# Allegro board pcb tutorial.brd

Outline 100 x 50 mm; copper layers: TOP, POWERPLANE_1, BOTTOM. Coordinates in mm from the lower left corner of the outline.
Outline path: rectangle 0,0 100,50

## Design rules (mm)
constraint set DEFAULT: min track width 0.127
net group DPD: nets D+ D-

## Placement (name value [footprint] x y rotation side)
C1  100uF  [1210]  6 27 0 top
C2  10uF  [0402-CAP]  13 33 270 top
C3  10uF  [0402-CAP]  35 11 180 top
C4  0.1uF  [0402-CAP]  4 22 0 top
C5  0.1uF  [0402-CAP]  4 19 0 top
C6  0.1uF  [0402-CAP]  2 38 90 top
C7  0.1uF  [0402-CAP]  34 18 90 top
C8  0.1uF  [0402-CAP]  5 38 90 top
C9  10uF  [0402-CAP]  11 25 180 top
IC1  PIC32MX440F512H  [SQFP-S-10X10-64]  22 25 90 top
JP1  -  [XTEND-DIGI-MODEM]  69 25 0 top
JP2  PIC 32 PROG  [1X06_LOCK]  11.43 15.24 0 top
MAIN_PWR  LED  [LED_LNJ]  19 5 270 top
NOREF  -  []  0 0 90 top
NOREF#2  -  [unnamed#2]  96 4 0 top
NOREF#3  -  [unnamed#2]  4 4 0 top
NOREF#4  -  []  0 0 0 top
NOREF#5  -  [unnamed#2]  4 46 0 top
NOREF#6  -  []  0 50 0 top
NOREF#7  -  []  0 0 0 top
NOREF#8  -  []  -24 -84 0 top
NOREF#9  -  [unnamed#2]  96 46 0 top
R1  150  [0402-RES]  16 5 270 top
R2  56K  [0402-RES]  35 14 0 top
U1  LT1965EMS8E-1.5PBF  [SOP65P490X110-9N]  7 33 0 top
X1  USB-B  [USB-MICROB]  19.05 46.35 180 top
Y1  8MHz  [CRYSTAL-SMD]  15 39 90 top

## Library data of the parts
C1-C9 = CAP NP
IC1 = PIC32MX440F512H
JP1 = XTEND-DIGI-MODEM
JP2 = M06_LOCK
MAIN_PWR = LED
R1 R2 = RESISTOR
U1 = LT1965EMS8E-1_0.5PBF
X1 = USB-MICROB
Y1 = CRYSTAL

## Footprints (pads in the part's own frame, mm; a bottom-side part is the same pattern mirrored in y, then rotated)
1X06_LOCK
  round 1.88 hole 1.016: 1(0,0) 2(2.54,-0.254) 3(5.08,0) 4(7.62,-0.254) 5(10.16,0) 6(12.7,-0.254)
0402-CAP
  rect 0.7x0.9 smd: 1(-0.65,0) 2(0.65,0)
0402-RES
  rect 0.7x0.9 smd: 1(-0.65,0) 2(0.65,0)
1210
  rect 1.2x2 smd: 1(-1.6,0) 2(1.6,0)
CRYSTAL-SMD
  rect 1.1x1.9 smd: 1(-1.15,1.85) 2(-1.15,-1.85) 3(1.15,-1.85) 4(1.15,1.85)
LED_LNJ
  rect 0.445x0.95 smd: 1(-0.652,0) 2(0.652,0)
SOP65P490X110-9N
  rect 1.425x0.45 smd: 1(-2.212,0.975) 2(-2.212,0.325) 3(-2.212,-0.325) 4(-2.212,-0.975) 5(2.212,-0.975) 6(2.212,-0.325) 7(2.212,0.325) 8(2.212,0.975)
  rect 1.68x1.88 smd: 9(0,0)
SQFP-S-10X10-64
  rect 1.6x0.295 smd: 1(-5.6,3.75) 2(-5.6,3.25) 3(-5.6,2.75) 4(-5.6,2.25) 5(-5.6,1.75) 6(-5.6,1.25) 7(-5.6,0.75) 8(-5.6,0.25) 9(-5.6,-0.25) 10(-5.6,-0.75) 11(-5.6,-1.25) 12(-5.6,-1.75) 13(-5.6,-2.25) 14(-5.6,-2.75) 15(-5.6,-3.25) 16(-5.6,-3.75) 33(5.6,-3.75) 34(5.6,-3.25) 35(5.6,-2.75) 36(5.6,-2.25) 37(5.6,-1.75) 38(5.6,-1.25) 39(5.6,-0.75) 40(5.6,-0.25) 41(5.6,0.25) 42(5.6,0.75) 43(5.6,1.25) 44(5.6,1.75) 45(5.6,2.25) 46(5.6,2.75) 47(5.6,3.25) 48(5.6,3.75)
  rect 0.295x1.6 smd: 17(-3.75,-5.6) 18(-3.25,-5.6) 19(-2.75,-5.6) 20(-2.25,-5.6) 21(-1.75,-5.6) 22(-1.25,-5.6) 23(-0.75,-5.6) 24(-0.25,-5.6) 25(0.25,-5.6) 26(0.75,-5.6) 27(1.25,-5.6) 28(1.75,-5.6) 29(2.25,-5.6) 30(2.75,-5.6) 31(3.25,-5.6) 32(3.75,-5.6) 49(3.75,5.6) 50(3.25,5.6) 51(2.75,5.6) 52(2.25,5.6) 53(1.75,5.6) 54(1.25,5.6) 55(0.75,5.6) 56(0.25,5.6) 57(-0.25,5.6) 58(-0.75,5.6) 59(-1.25,5.6) 60(-1.75,5.6) 61(-2.25,5.6) 62(-2.75,5.6) 63(-3.25,5.6) 64(-3.75,5.6)
unnamed#2
  round 4.064 hole 3.81: (0,0)
USB-MICROB
  rect 0.35x1.4 smd: D+(0,2.65) D-(-0.65,2.65) GND(1.3,2.65) ID(0.65,2.65) VBUS(-1.3,2.65)
  rect 1.8x1.9 smd: MT1(-3.8,0) MT2(3.8,0)
  rect 2.1x1.6 smd: MT3(-3.1,2.55) MT4(3.1,2.55)
  rect 1.9x1.9 smd: P_1(-1.2,0) P_2(1.2,0)
XTEND-DIGI-MODEM
  round 0 hole 3.3 unplated: (-26.5,14.5) (-26.5,-14.5) (26.5,14.5) (26.5,-14.5)
  round 1.422 hole 0.7: 1(-27.5,9) 2(-25.5,9) 3(-27.5,7) 4(-25.5,7) 5(-27.5,5) 6(-25.5,5) 7(-27.5,3) 8(-25.5,3) 9(-27.5,1) 10(-25.5,1) 11(-27.5,-1) 12(-25.5,-1) 13(-27.5,-3) 14(-25.5,-3) 15(-27.5,-5) 16(-25.5,-5) 17(-27.5,-7) 18(-25.5,-7) 19(-27.5,-9) 20(-25.5,-9)

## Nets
3.3V: C1.1 C4.1 C5.1 C6.1 C7.1 C8.1 IC1.10 IC1.19 IC1.26 IC1.35 IC1.38 JP2.2 R1.1 R2.1 U1.1 U1.2 U1.3
GND: C1.2 C2.2 C3.2 C4.2 C5.2 C6.2 C7.2 C8.2 C9.2 IC1.9 IC1.20 IC1.25 IC1.41 JP1.1 JP2.3 MAIN_PWR.1(CATHODE) U1.4 U1.5 U1.9 X1.GND Y1.2 Y1.4(GND_4)
VBUS: C2.1 IC1.34 JP1.2(VCC) U1.6(S\H\D\N\) U1.7 U1.8 X1.VBUS
CTS: IC1.21 JP1.9
D+: IC1.37 X1.D+
D-: IC1.36 X1.D-
PROG0: IC1.17 JP2.5
PROG1: IC1.18 JP2.4
RESET: IC1.7(_MCLR) JP2.1
RTS: IC1.29 JP1.10
SHDN: IC1.59 JP1.7
URX: IC1.31 JP1.6
UTX: IC1.32 JP1.5
N05718: C3.1 JP1.11 R2.2
N05832: MAIN_PWR.2 R1.2
N05985: IC1.39 Y1.1
N05997: IC1.40 Y1.3
N06072: C9.1 IC1.56

Pads without a net: IC1 1 2 3 4 5 6 8 11 12 13 14 15 16 22 23 24 27 28 30 33 42 43 44 45 46 47 48 49 50 51 52 53 54 55 57 58 60 61 62 63 64; JP1 3 4 8 12 13 14 15 16 17 18 19 20; JP2 6; X1 ID MT1 MT2 MT3 MT4 P_1 P_2

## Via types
v1: diameter 0.61, hole 0.33, TOP to BOTTOM, 34 vias

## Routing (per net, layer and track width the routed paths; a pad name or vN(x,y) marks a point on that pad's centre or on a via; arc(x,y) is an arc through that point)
3.3V: length 20.7
  TOP w0.28: IC1.10 v1(22.75,17.63) ; IC1.38 v1(23.25,31.83) ; IC1.19 v1(28.83,22.25) ; IC1.26 v1(29.37,25.75) ; IC1.35 v1(24.75,31.83)
  TOP w0.381: R2.1 v1(33.57,14) ; C1.1 v1(3.37,27) ; C4.1 v1(2.57,22) ; R1.1 v1(16,6.43) ; C7.1 v1(34,16.57) ; C5.1 v1(2.57,19) ; U1.3 U1.2 U1.1 v1(3.64,33.98) ; C8.1 v1(5,36.57) ; C6.1 v1(2,36.57)
  POWERPLANE_1 w0.381: JP2.2 13.97,16.1 ; JP2.2 13.97,13.87 ; JP2.2 12.85,14.99 ; JP2.2 15.09,14.99
GND: length 29.2
  TOP w0.28: IC1.9 v1(22.25,20.95) ; IC1.41 v1(21.75,31.83) ; IC1.25 v1(26.25,25.25) ; IC1.20 v1(25.62,22.75)
  TOP w0.381: X1.GND v1(17.75,42.57) ; C4.2 v1(5.43,22) ; U1.9 v1(7,34.37) ; C7.2 v1(34,19.43) ; MAIN_PWR.1 v1(19,6.31) ; Y1.2 v1(18.23,37.85) ; C1.2 v1(8.63,27) ; C5.2 v1(5.43,19) ; C2.2 v1(13,31.57) ; C8.2 v1(5,39.43) ; C3.2 v1(33.57,11) ; U1.5 v1(10.36,32.02) ; U1.4 v1(3.64,32.02) ; C6.2 v1(2,39.43) ; Y1.4 v1(13.15,41.13) ; C9.2 v1(9.57,25)
  BOTTOM w0.381: JP2.3 16.51,16.36 ; JP2.3 17.63,15.24 ; JP2.3 16.51,14.12 ; JP2.3 15.39,15.24 ; JP1.1 41.5,34.89 ; JP1.1 42.39,34 ; JP1.1 40.61,34 ; JP1.1 41.5,33.11
VBUS: length 55.8
  TOP w0.127: U1.6 U1.7 U1.8 12.03,33.98 12.36,33.65 C2.1 13.1,33.65 18.18,28.57 24.21,28.57 25.25,29.61 IC1.34 25.25,35.56 ; JP1.2 41.94,35.56 25.25,35.56 ; 25.25,35.56 25.25,38.25 24.13,39.37 22.86,39.37 20.35,41.88 X1.VBUS
CTS: length 15
  TOP w0.127: IC1.21 33,23.25 35.75,26 JP1.9
D+: length 15.9
  TOP w0.127: IC1.37 23.75,31.59 23.87,31.72 23.87,38 23.39,38.48 22.12,38.48 19.25,41.35 19.25,42.62 19.05,42.81 X1.D+
D-: length 15.9
  TOP w0.127: X1.D- 19.7,42.81 19.5,42.62 19.5,41.46 22.23,38.73 23.5,38.73 24.13,38.1 24.13,31.72 24.25,31.59 IC1.36
PROG0: length 10
  TOP w0.127: IC1.17 27.6,18.71 26.04,17.14 23.5,17.14 JP2.5
PROG1: length 13.2
  TOP w0.127: JP2.4 20.43,16.37 22.36,16.37 23.77,17.78 26.04,17.78 26.67,18.41 26.67,20.96 26.61,21.02 26.61,21.48 26.88,21.75 IC1.18
RESET: length 12.1
  TOP w0.127: IC1.7 21.25,18.41 19.99,17.14 13.34,17.14 JP2.1
RTS: length 16.4
  TOP w0.127: JP1.10 42.6,26.9 28.94,26.9 28.59,27.25 IC1.29
SHDN: length 88.6
  TOP w0.127: JP1.7 42.14,27.36 42.86,27.36 43.13,27.1 44.87,27.1 46.58,25.39 46.58,6.34 42.77,2.54 12.29,2.54 7.62,7.2 7.62,16.29 15.09,23.75 IC1.59
URX: length 16.6
  TOP w0.127: IC1.31 30.38,28.25 31.23,29.1 42.6,29.1 JP1.6
UTX: length 14.6
  TOP w0.127: IC1.32 27.6,29.09 28.51,30 JP1.5
N05718: length 15.4
  TOP w0.127: C3.1 R2.2 35.65,18.15 JP1.11
N05832: length 3
  TOP w0.127: R1.2 16.64,4.35 16.64,4.35 MAIN_PWR.2
N05985: length 16.5
  TOP w0.127: IC1.39 22.75,29.61 22.35,29.2 18.43,29.2 17.36,30.27 17.36,34.03 13.55,37.85 Y1.1
N05997: length 13.7
  TOP w0.127: Y1.3 20.09,40.15 22.25,37.99 IC1.40
N06072: length 4.9
  TOP w0.127: C9.1 15.16,25 15.41,25.25 IC1.56

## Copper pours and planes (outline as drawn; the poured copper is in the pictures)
3.3V on POWERPLANE_1: 0.3,49.7 99.7,49.7 99.7,0.3 0.3,0.3
GND on BOTTOM: 0.3,49.7 99.7,49.7 99.7,0.3 0.3,0.3

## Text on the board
User.Comments: EMA DESIGN AUTOMATION | 225 TECH PARK DRIVE | ROCHESTER NY 14623 | A | EMA-123 | 1 OF 1
XSECTION_CHART: *  SURFACE | L1 TOP CONDUCTOR | *  DIELECTRIC | L2 POWERPLANE_1 PLANE | L3 BOTTOM CONDUCTOR | DESIGN CROSS SECTION CHART | ___________________________ | TOTAL THICKNESS 0.49784 MM | 1-3
DIMENSION: FIGURE | FINISHED_SIZE | 0.3302 | 0.7 | 1.016 | 3.81 | 3.3 | DRILL CHART: TOP to BOTTOM | ALL UNITS ARE IN MILLIMETERS | PLATED | NON-PLATED | QTY | 34 | 20 | 6 | 4
